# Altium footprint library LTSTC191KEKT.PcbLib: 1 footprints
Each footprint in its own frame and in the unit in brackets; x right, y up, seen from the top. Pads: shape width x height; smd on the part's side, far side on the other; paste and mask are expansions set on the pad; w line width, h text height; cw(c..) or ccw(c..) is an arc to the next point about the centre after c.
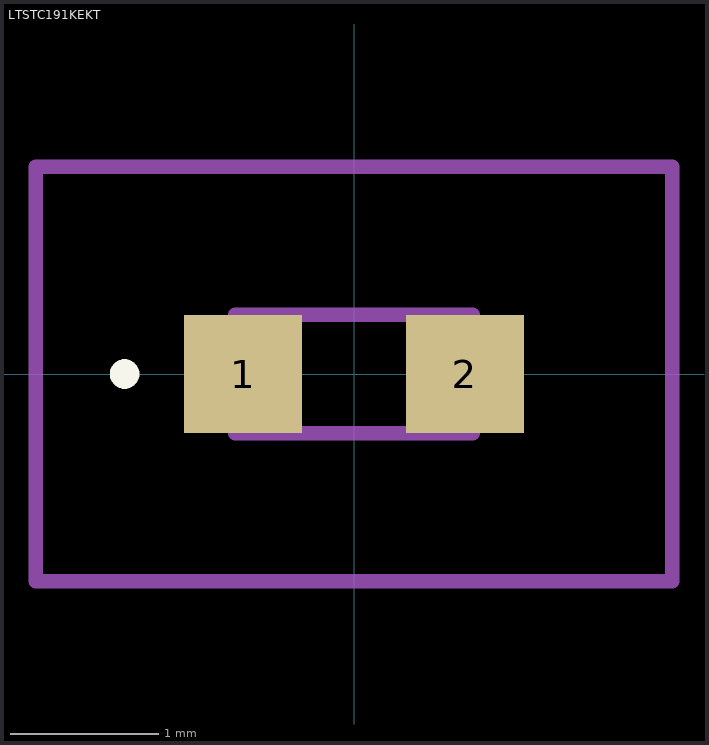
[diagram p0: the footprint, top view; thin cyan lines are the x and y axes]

## LTSTC191KEKT [mm]
pads (2):
  rect 0.8x0.8 smd: 1(-0.75,0) 2(0.75,0)
Top Overlay:
  lines w0.1: -1.6,0 -1.6,0 ; -1.6,0 ccw(c-1.55,0) -1.5,0 ; -1.6,0 cw(c-1.55,0) -1.5,0 ; -1.5,0 -1.5,0
Mechanical 15:
  lines w0.1: -0.8,-0.4 0.8,-0.4 0.8,0.4 -0.8,0.4 -0.8,-0.4
Mechanical 20:
  lines w0.1: -2.15,-1.4 2.15,-1.4 2.15,1.4 -2.15,1.4 -2.15,-1.4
